Omron CX-Programmer project NuevoProyecto (CX-Programmer 9.50)

# PLC NewPLC1: CP1L-E EM

## Program P6_1_GRAFCET2 (cyclic task 0)
Local symbols
Etapa_0 10.00 BOOL
Etapa_1 10.01 BOOL
Etapa_2 10.02 BOOL
Etapa_3 10.03 BOOL
Etapa_4 10.04 BOOL
Etapa_5 10.05 BOOL
F1 0.04 BOOL
F2 0.05 BOOL
FB 0.03 BOOL
FCP 0.06 BOOL
KB 100.01 BOOL
KS 100.00 BOOL
P1 0.01 BOOL
P2 0.02 BOOL
PB 0.00 BOOL

### Section Sección1_Programa_principal
; Programa principal (Etapas 0 ... 7)

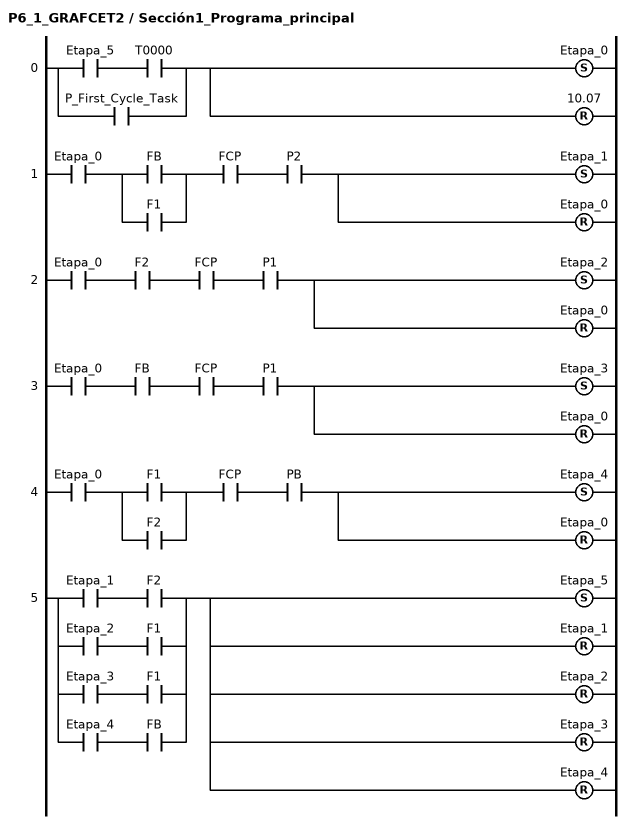
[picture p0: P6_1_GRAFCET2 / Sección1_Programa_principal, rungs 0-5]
; rung 0
LD Etapa_5
AND T0000
OR P_First_Cycle_Task
SET Etapa_0
RSET 10.07
; rung 1
LD Etapa_0
LD FB
OR F1
ANDLD
AND FCP
AND P2
SET Etapa_1
RSET Etapa_0
; rung 2
LD Etapa_0
AND F2
AND FCP
AND P1
SET Etapa_2
RSET Etapa_0
; rung 3
LD Etapa_0
AND FB
AND FCP
AND P1
SET Etapa_3
RSET Etapa_0
; rung 4
LD Etapa_0
LD F1
OR F2
ANDLD
AND FCP
AND PB
SET Etapa_4
RSET Etapa_0
; rung 5
LD Etapa_1
AND F2
LD Etapa_2
AND F1
ORLD
LD Etapa_3
AND F1
ORLD
LD Etapa_4
AND FB
ORLD
SET Etapa_5
RSET Etapa_1
RSET Etapa_2
RSET Etapa_3
RSET Etapa_4

### Section Sección2_Temporizador

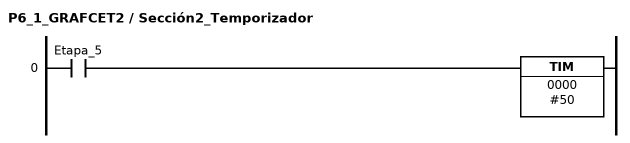
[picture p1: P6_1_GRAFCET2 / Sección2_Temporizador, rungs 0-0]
; rung 0
LD Etapa_5
TIM 0000 #50

### Section Sección3_Salidas

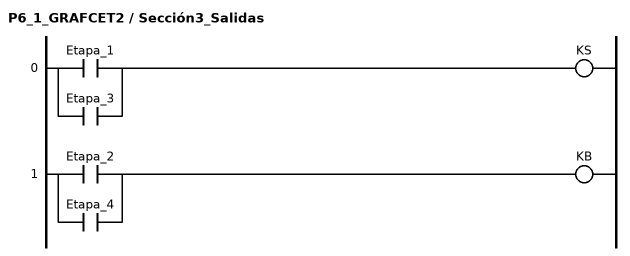
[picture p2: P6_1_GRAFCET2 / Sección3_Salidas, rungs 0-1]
; rung 0
LD Etapa_1
OR Etapa_3
OUT KS
; rung 1
LD Etapa_2
OR Etapa_4
OUT KB

### Section Sección4_END
; rung 0: Fin de programa
END(001)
